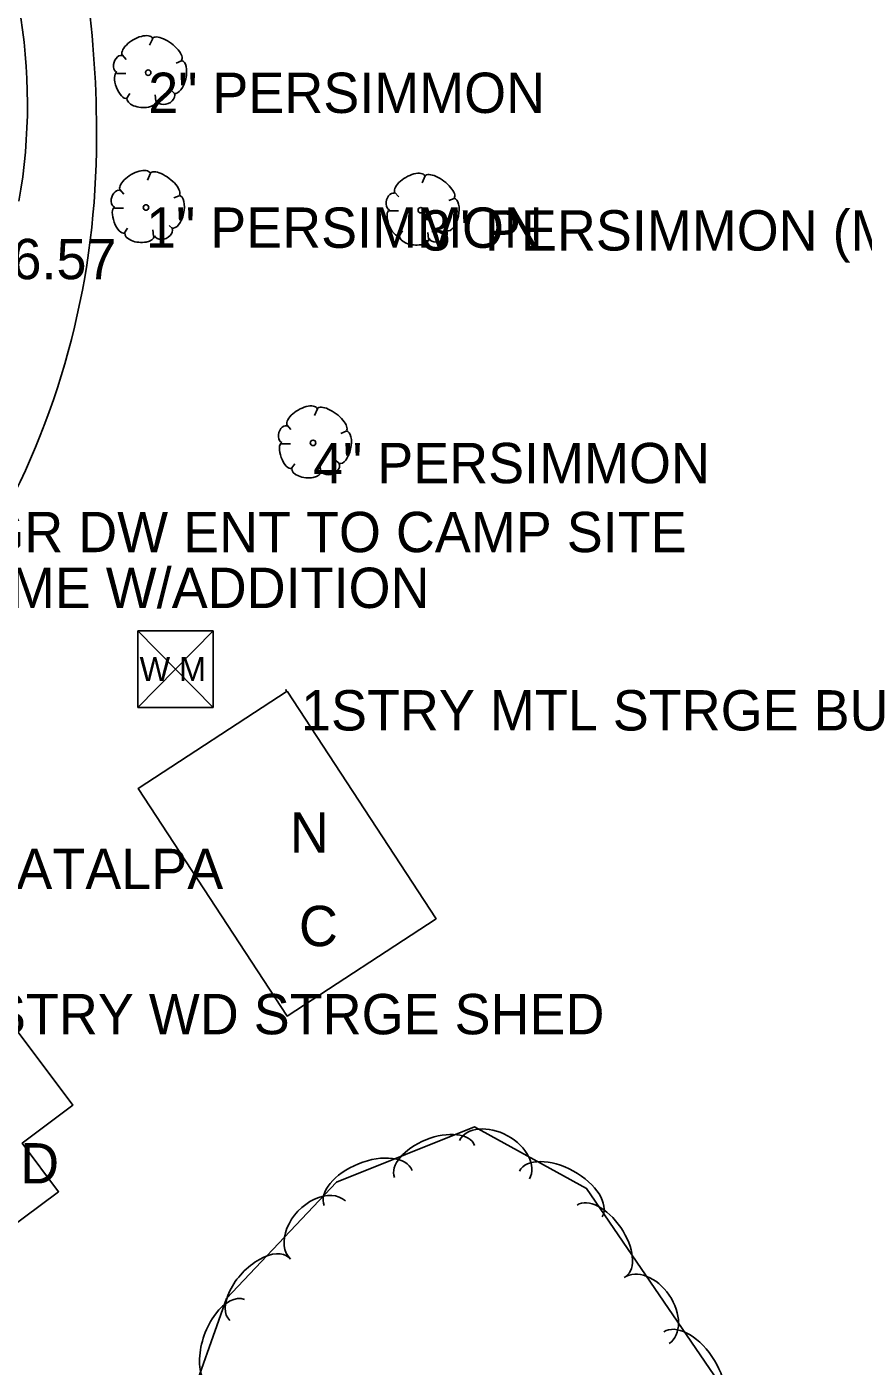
# Model space of a CAD drawing. Extents: x 1451369 to 1458940, y 1868647 to 1875095.
# Drawn here: x 1454644.6 to 1454748.2, y 1871458.6 to 1871624.7 of the extents above; entities that cross this region are included whole.
import ezdxf

# ---------------------------------------------------------------- set-up
doc = ezdxf.new("R2010")
doc.units = 0
for name, color, linetype in [('E_Property Line', 7, 'Continuous'), ('E_Quarter Section Line', 7, 'Continuous'), ('E_Row Point', 7, 'Continuous'), ('E_ROW Point Number', 7, 'Continuous'), ('S_BUILDING_ANNOT', 7, 'Continuous'), ('S_HIST_HIGH_WATER_ANNOT', 7, 'Continuous'), ('S_PARKING', 7, 'Continuous'), ('S_SURVEY_TEXT_ANNOT', 7, 'Continuous'), ('S_TREE_ANNOT', 7, 'Continuous')]:
    doc.layers.add(name, color=color, linetype=linetype)

msp = doc.modelspace()

# ---------------------------------------------------------------- linework, layer by layer
at = {"layer": 'E_Property Line'}
for points in [[(1454676.86, 1871542.31), (1454695.3, 1871514.09), (1454676.83, 1871502.02), (1454658.39, 1871530.24)], [(1454626.18, 1871497.22), (1454636.15, 1871504.7), (1454640.18, 1871499.32), (1454642.63, 1871501.16), (1454650.27, 1871490.96), (1454644, 1871486.26), (1454648.52, 1871480.23), (1454642.03, 1871475.37), (1454636.93, 1871482.19), (1454635.27, 1871480.95), (1454628.23, 1871490.34), (1454630.22, 1871491.83)]]:
    msp.add_lwpolyline(points, close=True, dxfattribs=at)
at = {"layer": 'E_Quarter Section Line'}
for p, q in [((1454658.35, 1871549.79), (1454667.69, 1871549.79)), ((1454658.35, 1871549.79), (1454658.35, 1871540.29)), ((1454658.35, 1871549.79), (1454667.69, 1871540.29)), ((1454667.69, 1871549.79), (1454658.35, 1871540.29)), ((1454667.69, 1871549.79), (1454667.69, 1871540.29)), ((1454658.35, 1871540.29), (1454667.69, 1871540.29))]:
    msp.add_line(p, q, dxfattribs=at)
at = {"layer": 'E_Row Point'}
msp.add_lwpolyline([(1454676.7, 1871542.43), (1454676.7, 1871542.48), (1454676.7, 1871542.43), (1454676.65, 1871542.43), (1454676.7, 1871542.43), (1454676.7, 1871542.38), (1454676.7, 1871542.43), (1454676.75, 1871542.43)], dxfattribs=at)
at = {"layer": 'E_ROW Point Number'}
for p, q in [((1454660.18, 1871623.24), (1454659.79, 1871622.39)), ((1454656.38, 1871621.23), (1454656.88, 1871620.65)), ((1454663.74, 1871620.45), (1454663.08, 1871620.18)), ((1454655.72, 1871618.9), (1454656.85, 1871618.9)), ((1454656.88, 1871615.73), (1454657.35, 1871616.42)), ((1454662.97, 1871616.35), (1454662.5, 1871616.77)), ((1454660.57, 1871615.45), (1454660.49, 1871616.23)), ((1454659.9, 1871606.52), (1454659.52, 1871605.67)), ((1454693.96, 1871606.19), (1454693.57, 1871605.34)), ((1454656.11, 1871604.51), (1454656.61, 1871603.93)), ((1454663.47, 1871603.73), (1454662.81, 1871603.46)), ((1454690.16, 1871604.17), (1454690.66, 1871603.59)), ((1454697.52, 1871603.4), (1454696.86, 1871603.13)), ((1454655.45, 1871602.18), (1454656.57, 1871602.18)), ((1454689.5, 1871601.85), (1454690.63, 1871601.85)), ((1454656.61, 1871599.01), (1454657.07, 1871599.7)), ((1454662.69, 1871599.63), (1454662.23, 1871600.05)), ((1454696.75, 1871599.29), (1454696.28, 1871599.72)), ((1454660.29, 1871598.73), (1454660.21, 1871599.51)), ((1454690.66, 1871598.67), (1454691.13, 1871599.37)), ((1454694.35, 1871598.4), (1454694.27, 1871599.17)), ((1454680.61, 1871577.33), (1454680.22, 1871576.48)), ((1454676.81, 1871575.32), (1454677.31, 1871574.74)), ((1454684.17, 1871574.54), (1454683.51, 1871574.27)), ((1454676.15, 1871572.99), (1454677.27, 1871572.99)), ((1454677.31, 1871569.82), (1454677.78, 1871570.51)), ((1454680.99, 1871569.54), (1454680.92, 1871570.32)), ((1454683.4, 1871570.44), (1454682.93, 1871570.86))]:
    msp.add_line(p, q, dxfattribs=at)
msp.add_lwpolyline([(1454975.93, 1871099.07), (1454929.38, 1871155.93), (1454884.06, 1871212.14), (1454844.07, 1871268.25), (1454818.62, 1871299.3), (1454787.11, 1871333), (1454773.6, 1871342.99), (1454759.62, 1871337.58), (1454743.68, 1871343.3), (1454729.62, 1871362.73), (1454720.26, 1871387.51), (1454710.54, 1871401.75), (1454695.23, 1871424.03), (1454676.94, 1871442.69), (1454664.33, 1871452.85), (1454669.34, 1871466.98), (1454682.96, 1871481.41), (1454700.06, 1871488.27), (1454713.94, 1871480.64), (1454733.1, 1871452.57), (1454750.83, 1871410.87), (1454764.22, 1871384.37), (1454779.73, 1871376.91), (1454787.43, 1871375.32)], dxfattribs=at)
for centre in [(1454659.62, 1871619), (1454659.35, 1871602.28), (1454693.4, 1871601.94), (1454680.05, 1871573.09)]:
    msp.add_circle(centre, 0.341, dxfattribs=at)
for centre, major_axis, ratio, start_param, end_param in [((1454658.28, 1871622.2), (1.86, 1.08), 0.471018, 0, 3.141593), ((1454661.94, 1871621.88), (-1.81, 1.36), 0.405113, 3.141593, 6.283186), ((1454656.05, 1871620.08), (0.31, 1.03), 0.646762, 0, 3.141593), ((1454663.29, 1871618.47), (0.46, 2.04), 0.482994, 3.141593, 6.283185), ((1454656.35, 1871617.43), (-0.61, 1.6), 0.420543, 6.283185, 9.424777), ((1454661.77, 1871615.95), (1.09, 0.46), 0.711534, 3.141592, 6.283185), ((1454658.81, 1871615.65), (-1.83, 0.19), 0.529943, 0, 3.141593), ((1454658.01, 1871605.48), (1.86, 1.08), 0.471018, 0, 3.141593), ((1454661.66, 1871605.16), (-1.81, 1.36), 0.405113, 3.141593, 6.283186), ((1454692.06, 1871605.14), (1.86, 1.08), 0.471018, 0, 3.141593), ((1454695.72, 1871604.82), (-1.81, 1.36), 0.405113, 3.141593, 6.283186), ((1454655.77, 1871603.37), (0.31, 1.03), 0.646762, 0, 3.141593), ((1454663.02, 1871601.75), (0.46, 2.04), 0.482994, 3.141593, 6.283185), ((1454689.83, 1871603.03), (0.31, 1.03), 0.646762, 0, 3.141593), ((1454697.07, 1871601.41), (0.46, 2.04), 0.482994, 3.141593, 6.283185), ((1454656.08, 1871600.71), (-0.61, 1.6), 0.420543, 6.283185, 9.424777), ((1454690.13, 1871600.38), (-0.61, 1.6), 0.420543, 6.283185, 9.424777), ((1454661.5, 1871599.23), (1.09, 0.46), 0.711534, 3.141592, 6.283185), ((1454658.54, 1871598.93), (-1.83, 0.19), 0.529943, 0, 3.141593), ((1454692.6, 1871598.6), (-1.83, 0.19), 0.529943, 0, 3.141593), ((1454695.55, 1871598.89), (1.09, 0.46), 0.711534, 3.141592, 6.283185), ((1454678.71, 1871576.29), (1.86, 1.08), 0.471018, 0, 3.141593), ((1454682.37, 1871575.97), (-1.81, 1.36), 0.405113, 3.141593, 6.283186), ((1454676.48, 1871574.17), (0.31, 1.03), 0.646762, 0, 3.141593), ((1454676.78, 1871571.52), (-0.61, 1.6), 0.420543, 6.283185, 9.424777), ((1454683.72, 1871572.56), (0.46, 2.04), 0.482994, 3.141593, 6.283185), ((1454679.24, 1871569.74), (-1.83, 0.19), 0.529943, 0, 3.141593), ((1454682.2, 1871570.04), (1.09, 0.46), 0.711534, 3.141592, 6.283185), ((1454702.52, 1871484.21), (-4.34, 2.39), 0.685306, 3.141593, 6.283185), ((1454695.11, 1871484), (-4.96, -1.99), 0.540644, 3.141593, 6.283185), ((1454686.88, 1871480.7), (-5.45, -2.19), 0.550024, 3.141593, 6.283185), ((1454710.76, 1871479.97), (-5.14, 2.83), 0.550076, 3.141593, 6.283185), ((1454680.65, 1871475.49), (-3.4, -3.6), 0.685225, 3.141577, 6.28317), ((1454715.8, 1871474.16), (-3.01, 4.42), 0.540696, 3.141593, 6.283185), ((1454673.39, 1871468.18), (-3.67, -3.89), 0.540632, 3.141583, 6.283176), ((1454721.39, 1871465.5), (-2.79, 4.09), 0.685306, 3.141593, 6.283185), ((1454669.6, 1871461.36), (-1.96, -5.53), 0.550022, 3.141575, 6.283168), ((1454726.82, 1871458), (-3.31, 4.85), 0.550076, 3.141593, 6.283185)]:
    msp.add_ellipse(centre, major_axis=major_axis, ratio=ratio, start_param=start_param, end_param=end_param, dxfattribs=at)
at = {"layer": 'S_PARKING'}
for centre, major_axis, ratio, start_param, end_param in [((1454575.72, 1871615.11), (-28.7, 62.69), 0.999843, 4.107391, 4.814042), ((1454540.09, 1871612.64), (-9.09, 117), 0.963705, 4.621808, 4.939609), ((1454557.46, 1871609.88), (17.63, 95.75), 0.982787, 4.384696, 4.900665)]:
    msp.add_ellipse(centre, major_axis=major_axis, ratio=ratio, start_param=start_param, end_param=end_param, dxfattribs=at)

# ---------------------------------------------------------------- texts
at = {"layer": 'E_Quarter Section Line'}
msp.add_text('W M', height=3, rotation=360, dxfattribs=at).set_placement((1454658.55, 1871543.55))
at = {"layer": 'S_BUILDING_ANNOT'}
for s, height, p in [('MBLHOME W/ADDITION', 5, (1454618.7, 1871552.62)), (' 1STRY MTL STRGE BU', 5, (1454676.7, 1871537.43)), ('N', 5, (1454677.18, 1871522.27)), ('C', 5, (1454678.3, 1871510.69)), ('1STRY WD STRGE SHED', 5, (1454636.29, 1871499.76)), ('SHED', 5.001, (1454630, 1871481.26))]:
    msp.add_text(s, height=height, dxfattribs=at).set_placement(p)
at = {"layer": 'S_HIST_HIGH_WATER_ANNOT'}
msp.add_text('HHW POINTED OUT BY PROPERTY OWN ELEV:176.57', height=5, dxfattribs=at).set_placement((1454483.3, 1871593.39))
at = {"layer": 'S_SURVEY_TEXT_ANNOT'}
msp.add_text('GR DW ENT TO CAMP SITE', height=5, dxfattribs=at).set_placement((1454639.06, 1871559.54))
at = {"layer": 'S_TREE_ANNOT'}
for s, p in [('2" PERSIMMON', (1454659.62, 1871614)), ('1" PERSIMMON', (1454659.35, 1871597.28)), ('3" PERSIMMON (MULTIPLE)', (1454693.4, 1871596.94)), ('4" PERSIMMON', (1454680.05, 1871568.09)), ('8" CATALPA', (1454630.5, 1871517.76))]:
    msp.add_text(s, height=5, dxfattribs=at).set_placement(p)

doc.saveas('drawing.dxf')
